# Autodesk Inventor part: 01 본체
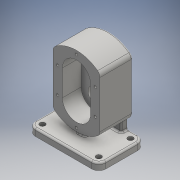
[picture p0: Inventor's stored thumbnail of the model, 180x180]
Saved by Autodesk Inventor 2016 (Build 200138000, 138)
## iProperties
Created: 2022-08
Part Number: 01 본체
Material: 일반
Document SubType Name: Modeling
Designer: 3sil_cad017
Density: 1 g/cm^3
Appearance: 기본값
Author: 3sil_cad017
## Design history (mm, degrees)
sketch "스케치1"
  geometry: L1 (0, -22)-(0, 22); L2 (24, -22)-(24, 22); L3 (-24, 22)-(-24, -22); L4 (-40, 44.721)-(-40, -44.721); L5 (40, 44.721)-(40, -44.721); A1 r 24 centre (0, -22) between (-24, -22) and (24, -22); A2 r 24 centre (0, 22) between (24, 22) and (-24, 22); A3 r 60 centre (0, 0) between (40, 44.721) and (-40, 44.721); A4 r 60 centre (0, 0) between (-40, -44.721) and (40, -44.721); 5 further points
  constraints: 12 end point, 8 point on circle, 4 centre point, 4 tangent, 2 coincident, 2 symmetric about line, 2 vertical, 1 concentric, 1 midpoint, 1 parallel, 1 other
  dimensions: "d0" = 44 distance of L1.start L1.end; "d1" = 24 radius of A2; "d2" = 80 distance between parallel lines of L4 L5; "d3" = 60 radius of A3
extrude "돌출1" new body sketch "스케치1" distance "d4" = 56; taper "d5" = 0 deg
node "작업 평면1"
sketch "스케치2"
  geometry: L1 (-60, 56)-(60, 56); L2 (60, 56)-(60, -22); L3 (60, -22)-(-60, -22); L4 (-60, -22)-(-60, 56); L5 (40, 56)-(-40, 56) reference; L6 (40, 0)-(-40, 0) reference; 3 further points
  constraints: 8 end point, 2 midpoint, 2 parallel, 1 horizontal, 1 perpendicular, 1 point on line, 1 vertical alignment
  dimensions: "d7" = 120 distance of L2.end L3.end; "d8" = 78 distance of L1.end L2.end
extrude "돌출2" join sketch "스케치2" distance "d9" = 12; taper "d10" = 0 deg
sketch "스케치3"
  geometry: L1 (32, 0)-(-32, 0); L2 (-32, 0)-(-32, 80); L3 (-32, 80)-(32, 80); L4 (32, 80)-(32, 0); L5 (-60, 80)-(60, 80) reference; 2 further points
  constraints: 8 end point, 2 coincident, 2 parallel, 1 horizontal, 1 midpoint, 1 perpendicular, 1 point on line
  dimensions: "d11" = 64 distance between parallel lines of L2 L4
extrude "돌출3" join sketch "스케치3" distance "d12" = 12; taper "d13" = 0 deg
sketch "스케치4"
  geometry: L1 (8, -55.833)-(8, -66.773); L2 (56, -68)-(56, -50.754) reference; 1 further point
  constraints: 2 end point, 1 vertical
  dimensions: "d14" = 48 distance between parallel lines of L1 L2
feature "리브1" sketch "스케치4" dims "d15" = 1, "d16" = 12, "d17" = 0, "d18" = 0, "d19" = 1, "d20" = 1
fillet "모깎기1" dims "d21" = 12
sketch "스케치5"
  geometry: A1 r 12 centre (-48, 44) between (-48, 56) and (-60, 44) reference; A2 r 12 centre (-48, -10) between (-60, -10) and (-48, -22) reference; A3 r 12 centre (48, -10) between (48, -22) and (60, -10) reference; A4 r 12 centre (48, 44) between (60, 44) and (48, 56) reference; 5 further points
  constraints: 4 coincident
hole "구멍1" sketch "스케치5" at (-48, 44), (48, 44), (48, -10), (-48, -10) diameter "d22" = 9; stored, may be unused: countersink angle "d26" = 90 deg, drill point angle "d28" = 118 deg; dims "d23" = 6, "d24" = 4, "d25" = 2, "d27" = 8
sketch "스케치6"
  geometry: C1 r 19 at (0, -22); 1 further point
  constraints: 1 centre point, 1 vertical alignment
  dimensions: "d29" = 22 distance of C1.centre point (0, 0); "d30" = 38 diameter of C1
extrude "돌출4" join sketch "스케치6" distance "d31" = 12; taper "d32" = 0 deg
extrude "돌출5" cut sketch "스케치1" distance "d33" = 32; taper "d34" = 0 deg
sketch "스케치7"
  geometry: L1 (-24, -22)-(-24, 22) reference; L2 (24, 22)-(24, -22) reference; A1 r 24 centre (0, -22) between (-24, -22) and (24, -22) reference; A2 r 24 centre (0, 22) between (24, 22) and (-24, 22) reference; 3 further points
  constraints: 2 coincident
hole "구멍2" sketch "스케치7" at (0, 22), (0, -22) diameter "d35" = 25; stored, may be unused: countersink angle "d39" = 90 deg, drill point angle "d41" = 0 deg; dims "d36" = 6, "d37" = 4, "d38" = 2, "d40" = 15
sketch "스케치8"
  geometry: C1 r 12.5 at (0, -22) reference; 2 further points
  constraints: 1 coincident
hole "구멍3" sketch "스케치8" at (0, -22) diameter "d42" = 16; stored, may be unused: countersink angle "d46" = 90 deg, drill point angle "d48" = 118 deg; dims "d43" = 6, "d44" = 4, "d45" = 2, "d47" = 15
sketch "스케치9"
  geometry: C1 r 12.5 at (0, 0) reference; 2 further points
  constraints: 1 coincident
hole "구멍4" sketch "스케치9" at (0, 0) diameter "d49" = 17; stored, may be unused: countersink angle "d53" = 90 deg, drill point angle "d55" = 118 deg; dims "d50" = 6, "d51" = 4, "d52" = 2, "d54" = 15
sketch "스케치10"
  geometry: C1 r 8.5 at (0, 0) reference; C2 r 14 at (0, 0); 1 further point
  constraints: 1 centre point, 1 coincident
  dimensions: "d56" = 28 diameter of C2
extrude "돌출6" cut sketch "스케치10" distance "d57" = 8.3; taper "d58" = 0 deg
sketch "스케치11"
  geometry: L1 (-24, -22)-(-24, 22) reference; L2 (24, 22)-(24, -22) reference; L3 (32, 22)-(32, -22); L4 (-32, -22)-(-32, 22); A1 r 24 centre (0, 22) between (24, 22) and (-24, 22) reference; A2 r 24 centre (0, -22) between (-24, -22) and (24, -22) reference; A3 r 32 centre (0, 22) between (32, 22) and (-32, 22); A4 r 32 centre (0, -22) between (-32, -22) and (32, -22); 7 further points
  constraints: 6 point on circle, 4 coincident, 4 end point, 2 centre point, 3 other
  dimensions: "d59" = 32 radius of A3
hole "구멍5" sketch "스케치11" at (-32, 22), (32, 22), (-32, -22), (32, -22), (0, -54), (0, 54) diameter "d60" = 4.134; stored, may be unused: countersink angle "d64" = 90 deg, drill point angle "d66" = 118 deg; dims "d61" = 10, "d62" = 4, "d63" = 2, "d65" = 12
fillet "모깎기2" dims "d67" = 0.5
chamfer "모따기1" distance "d68" = 0.8; stored, may be unused: second distance "d69" = 2, angle "d70" = 30 deg
fillet "모깎기3" dims "d71" = 10
fillet "모깎기4" dims "d72" = 3
fillet "모깎기5" dims "d73" = 3
fillet "모깎기6" dims "d74" = 3
fillet "모깎기7" dims "d75" = 3
node "솔리드1"
node "투영된 루프1"
node "투영된 루프2"
